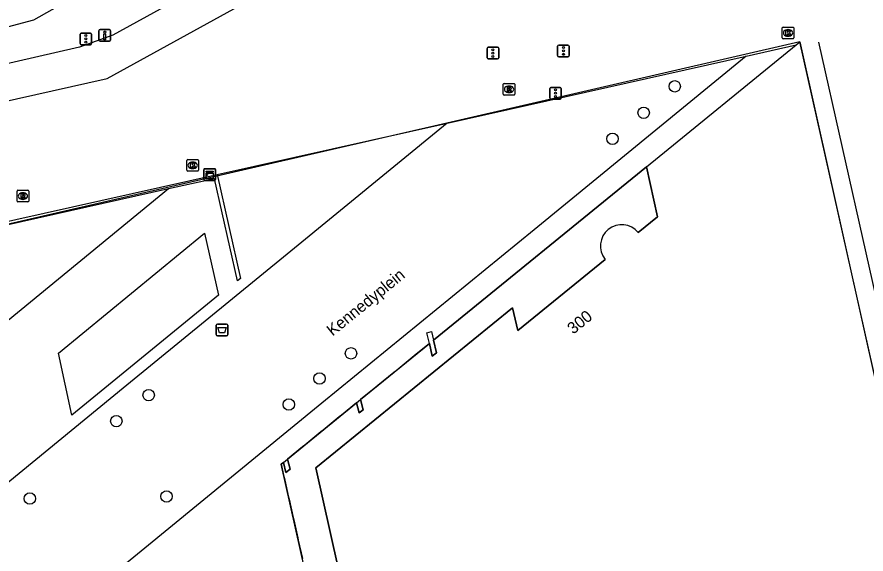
# Model space of a CAD drawing. Extents: x 160806 to 161707, y 383697 to 384148.
# Drawn here: x 161489.3 to 161561.9, y 383910.2 to 383956.1 of the extents above; entities that cross this region are included whole.
import ezdxf

# ---------------------------------------------------------------- set-up
doc = ezdxf.new("R2010")
doc.units = 0
for name, color, linetype in [('IMGEO_Afvalbak', 7, 'Continuous'), ('IMGEO_Boom', 7, 'Continuous'), ('IMGEO_Drukknoppaal', 7, 'Continuous'), ('IMGEO_Kast', 7, 'Continuous'), ('IMGEO_Kolk', 7, 'Continuous'), ('IMGEO_Lijnafwatering', 7, 'Continuous'), ('IMGEO_Muur', 7, 'Continuous'), ('IMGEO_Openbare_ruimte_label', 7, 'Continuous'), ('IMGEO_OVBaan_gesloten', 7, 'Continuous'), ('IMGEO_Pand', 7, 'Continuous'), ('IMGEO_Pand_nummerreeks', 7, 'Continuous'), ('IMGEO_Pand_overbouw', 7, 'Continuous'), ('IMGEO_Rijbaan_lokaal_gesloten', 7, 'Continuous'), ('IMGEO_Rioolput', 7, 'Continuous'), ('IMGEO_Verkeersregelinstallatiepaal', 7, 'Continuous'), ('IMGEO_Voetpad_open', 7, 'Continuous')]:
    doc.layers.add(name, color=color, linetype=linetype)

msp = doc.modelspace()

# ---------------------------------------------------------------- linework, layer by layer
at = {"layer": 'IMGEO_Afvalbak'}
for p, q in [((161506.372, 383928.933), (161506.372, 383929.733)), ((161506.372, 383929.733), (161506.372, 383928.933)), ((161506.472, 383929.833), (161507.262, 383929.833)), ((161507.262, 383929.833), (161506.472, 383929.833)), ((161507.362, 383929.733), (161507.362, 383928.933)), ((161507.362, 383928.933), (161507.362, 383929.733)), ((161507.262, 383928.833), (161506.472, 383928.833)), ((161506.472, 383928.833), (161507.262, 383928.833))]:
    msp.add_line(p, q, dxfattribs=at)
msp.add_lwpolyline([(161506.515, 383929.547), (161507.219, 383929.547), (161507.07, 383929.077), (161506.664, 383929.077), (161506.515, 383929.547)], dxfattribs=at)
for centre, start, end in [((161506.472, 383929.733), 90, 180), ((161506.472, 383929.733), 90, 180), ((161507.262, 383929.733), 0, 90), ((161507.262, 383929.733), 360, 90), ((161506.472, 383928.933), 180, 270), ((161506.472, 383928.933), 180, 270), ((161507.262, 383928.933), 270, 0), ((161507.262, 383928.933), 270, 0)]:
    msp.add_arc(centre, 0.1, start, end, dxfattribs=at)
at = {"layer": 'IMGEO_Boom'}
for centre in [(161545.585, 383950.166), (161542.926, 383947.907), (161540.266, 383945.685), (161517.898, 383927.324), (161515.202, 383925.175), (161500.593, 383923.754), (161512.579, 383922.952), (161497.824, 383921.531), (161490.429, 383914.901), (161502.123, 383915.083)]:
    msp.add_circle(centre, 0.489, dxfattribs=at)
at = {"layer": 'IMGEO_Drukknoppaal'}
for p, q in [((161496.34, 383954.127), (161496.34, 383954.927)), ((161496.34, 383954.927), (161496.34, 383954.127)), ((161496.44, 383955.027), (161497.23, 383955.027)), ((161497.23, 383955.027), (161496.44, 383955.027)), ((161497.33, 383954.927), (161497.33, 383954.127)), ((161497.33, 383954.127), (161497.33, 383954.927)), ((161497.23, 383954.027), (161496.44, 383954.027)), ((161496.44, 383954.027), (161497.23, 383954.027))]:
    msp.add_line(p, q, dxfattribs=at)
msp.add_lwpolyline([(161496.91, 383954.652), (161496.91, 383954.152), (161496.76, 383954.152), (161496.76, 383954.652), (161496.91, 383954.652)], dxfattribs=at)
msp.add_circle((161496.835, 383954.817), 0.085, dxfattribs=at)
for centre, start, end in [((161496.44, 383954.927), 90, 180), ((161496.44, 383954.927), 90, 180), ((161497.23, 383954.927), 0, 90), ((161497.23, 383954.927), 360, 90), ((161496.44, 383954.127), 180, 270), ((161496.44, 383954.127), 180, 270), ((161497.23, 383954.127), 270, 0), ((161497.23, 383954.127), 270, 0)]:
    msp.add_arc(centre, 0.1, start, end, dxfattribs=at)
at = {"layer": 'IMGEO_Kast'}
for p, q in [((161505.305, 383942.198), (161505.305, 383943.039)), ((161505.305, 383943.039), (161505.305, 383942.198)), ((161505.38, 383943.123), (161506.221, 383943.123)), ((161506.221, 383943.123), (161505.38, 383943.123)), ((161506.305, 383943.048), (161506.305, 383942.207)), ((161506.305, 383942.207), (161506.305, 383943.048)), ((161506.23, 383942.123), (161505.389, 383942.123)), ((161505.389, 383942.123), (161506.23, 383942.123))]:
    msp.add_line(p, q, dxfattribs=at)
for points in [[(161505.5, 383942.913), (161506.1, 383942.913), (161506.1, 383942.828), (161505.5, 383942.828), (161505.5, 383942.913)], [(161505.5, 383942.738), (161506.1, 383942.738), (161506.1, 383942.249), (161505.5, 383942.249), (161505.5, 383942.738)]]:
    msp.add_lwpolyline(points, dxfattribs=at)
msp.add_circle((161505.584, 383942.587), 0.0377, dxfattribs=at)
for centre, start, end in [((161505.383, 383943.045), 92.4484, 184.28452), ((161505.383, 383943.045), 92.4484, 184.28452), ((161506.227, 383943.045), 2.4484, 94.28452), ((161506.227, 383943.045), 2.4484, 94.28452), ((161505.383, 383942.201), 182.4484, 274.28452), ((161505.383, 383942.201), 182.4484, 274.28452), ((161506.227, 383942.201), 272.4484, 4.28452), ((161506.227, 383942.201), 272.4484, 4.28452)]:
    msp.add_arc(centre, 0.0779, start, end, dxfattribs=at)
at = {"layer": 'IMGEO_Kolk'}
for p, q in [((161554.774, 383954.312), (161554.774, 383955.164)), ((161554.849, 383955.238), (161555.701, 383955.238)), ((161555.262, 383955.018), (161555.287, 383955.018)), ((161555.775, 383955.164), (161555.775, 383954.312)), ((161555.701, 383954.238), (161554.849, 383954.238)), ((161555.285, 383954.458), (161555.26, 383954.458)), ((161503.856, 383942.985), (161503.856, 383943.837)), ((161503.931, 383943.911), (161504.783, 383943.911)), ((161504.344, 383943.691), (161504.369, 383943.691)), ((161504.857, 383943.837), (161504.857, 383942.985)), ((161504.783, 383942.911), (161503.931, 383942.911)), ((161504.367, 383943.131), (161504.342, 383943.131))]:
    msp.add_line(p, q, dxfattribs=at)
for points in [[(161554.774, 383954.312), (161554.774, 383955.164)], [(161554.849, 383955.238), (161555.701, 383955.238)], [(161555.095, 383954.938), (161555.218, 383954.938), (161555.218, 383954.787), (161555.348, 383954.938), (161555.512, 383954.938), (161555.366, 383954.787), (161555.519, 383954.538), (161555.367, 383954.538), (161555.282, 383954.702), (161555.218, 383954.635), (161555.218, 383954.538), (161555.095, 383954.538), (161555.095, 383954.938)], [(161555.775, 383955.164), (161555.775, 383954.312)], [(161555.701, 383954.238), (161554.849, 383954.238)], [(161503.856, 383942.985), (161503.856, 383943.837)], [(161503.931, 383943.911), (161504.783, 383943.911)], [(161504.177, 383943.611), (161504.3, 383943.611), (161504.3, 383943.46), (161504.43, 383943.611), (161504.594, 383943.611), (161504.448, 383943.46), (161504.601, 383943.211), (161504.449, 383943.211), (161504.364, 383943.375), (161504.3, 383943.308), (161504.3, 383943.211), (161504.177, 383943.211), (161504.177, 383943.611)], [(161504.857, 383943.837), (161504.857, 383942.985)], [(161504.783, 383942.911), (161503.931, 383942.911)]]:
    msp.add_lwpolyline(points, dxfattribs=at)
for centre, start, end in [((161554.851, 383955.162), 91.55205, 178.44795), ((161554.851, 383955.162), 91.55205, 178.44795), ((161555.699, 383955.162), 1.55205, 88.44795), ((161555.699, 383955.162), 1.55205, 88.44795), ((161554.851, 383954.314), 181.55205, 268.44795), ((161554.851, 383954.314), 181.55205, 268.44795), ((161555.699, 383954.314), 271.55205, 358.44795), ((161555.699, 383954.314), 271.55205, 358.44795), ((161503.933, 383943.835), 91.55205, 178.44795), ((161503.933, 383943.835), 91.55205, 178.44795), ((161504.781, 383943.835), 1.55205, 88.44795), ((161504.781, 383943.835), 1.55205, 88.44795), ((161503.933, 383942.987), 181.55205, 268.44795), ((161503.933, 383942.987), 181.55205, 268.44795), ((161504.781, 383942.987), 271.55205, 358.44795), ((161504.781, 383942.987), 271.55205, 358.44795)]:
    msp.add_arc(centre, 0.0765, start, end, dxfattribs=at)
for centre, major_axis, ratio, start_param, end_param in [((161555.261, 383954.738), (-0.387, 0.002), 0.722429, 4.712389, 7.853982), ((161555.286, 383954.738), (-0.39, 0.002), 0.717154, 1.570796, 4.712389), ((161504.343, 383943.411), (-0.387, 0.002), 0.722429, 4.712389, 7.853982), ((161504.368, 383943.411), (-0.39, 0.002), 0.717154, 1.570796, 4.712389)]:
    msp.add_ellipse(centre, major_axis=major_axis, ratio=ratio, start_param=start_param, end_param=end_param, dxfattribs=at)
at = {"layer": 'IMGEO_Lijnafwatering'}
for points in [[(161557.895, 383953.938), (161561.936, 383935.924)], [(161551.704, 383952.753), (161533.558, 383937.906)], [(161526.128, 383947.032), (161512.429, 383935.821)], [(161502.28, 383941.387), (161486.939, 383928.817)], [(161533.558, 383937.906), (161515.412, 383923.059)], [(161512.429, 383935.821), (161498.731, 383924.609)], [(161561.936, 383935.924), (161565.976, 383917.91)], [(161498.731, 383924.609), (161485.032, 383913.398)], [(161515.412, 383923.059), (161497.266, 383908.212)]]:
    msp.add_lwpolyline(points, dxfattribs=at)
at = {"layer": 'IMGEO_Muur'}
for points in [[(161454.756, 383931.084), (161506.454, 383942.63)], [(161506.454, 383942.63), (161508.439, 383933.738), (161508.183, 383933.535), (161506.222, 383942.268), (161502.28, 383941.387), (161484.102, 383937.319), (161484.378, 383936.019), (161477.167, 383934.318), (161476.856, 383935.709), (161454.819, 383930.799)]]:
    msp.add_lwpolyline(points, dxfattribs=at)
at = {"layer": 'IMGEO_OVBaan_gesloten'}
msp.add_lwpolyline([(161480.443, 383953.13), (161490.782, 383955.856), (161498.607, 383960.307), (161519.443, 383971.749)], dxfattribs=at)
at = {"layer": 'IMGEO_Pand'}
for points in [[(161543.162, 383943.281), (161555.972, 383953.708)], [(161555.972, 383953.708), (161556.299, 383953.974), (161562.871, 383924.395), (161563.33, 383924.497), (161577.028, 383863.632), (161576.544, 383863.524)], [(161543.162, 383943.281), (161544.114, 383939.013), (161542.463, 383937.675)], [(161539.638, 383935.367), (161532.156, 383929.275), (161531.72, 383931.221), (161514.903, 383917.532), (161521.152, 383889.432), (161518.425, 383888.826)], [(161524.603, 383928.164), (161524.393, 383929.092), (161524.791, 383929.187), (161524.957, 383928.451)], [(161524.603, 383928.164), (161524.849, 383927.077), (161525.203, 383927.357), (161524.957, 383928.451)], [(161518.377, 383923.091), (161518.722, 383923.384)], [(161518.377, 383923.091), (161518.585, 383922.232), (161518.924, 383922.501), (161518.722, 383923.384)], [(161512.128, 383917.99), (161512.48, 383918.284)], [(161512.128, 383917.99), (161512.33, 383917.119), (161512.682, 383917.413), (161512.48, 383918.284)]]:
    msp.add_lwpolyline(points, dxfattribs=at)
msp.add_arc((161541.06, 383936.509), 1.824, 39.719, 218.77804, dxfattribs=at)
at = {"layer": 'IMGEO_Pand_overbouw'}
msp.add_lwpolyline([(161576.544, 383863.524), (161556.299, 383953.974), (161403.923, 383918.874), (161417.58, 383859.039), (161456.542, 383836.683)], close=True, dxfattribs=at)
for points in [[(161542.463, 383937.675), (161544.114, 383939.013), (161543.162, 383943.281), (161524.957, 383928.451), (161525.203, 383927.357), (161524.849, 383927.077), (161524.603, 383928.164), (161523.307, 383927.113), (161523.125, 383926.96), (161521.751, 383925.839), (161521.569, 383925.688), (161520.187, 383924.579), (161520.009, 383924.429), (161518.722, 383923.384), (161518.924, 383922.501), (161518.585, 383922.232), (161518.377, 383923.091), (161517.073, 383922.029), (161516.886, 383921.882), (161515.513, 383920.754), (161515.329, 383920.601), (161513.944, 383919.481), (161513.761, 383919.329), (161512.48, 383918.284), (161512.682, 383917.413), (161512.33, 383917.119), (161512.128, 383917.99)], [(161521.152, 383889.432), (161514.903, 383917.532), (161531.72, 383931.221), (161532.156, 383929.275), (161539.638, 383935.367)], [(161512.128, 383917.99), (161511.932, 383917.834), (161512.164, 383916.794), (161512.207, 383916.608), (161512.559, 383915.03), (161512.602, 383914.843), (161512.953, 383913.273), (161512.995, 383913.087), (161513.344, 383911.529), (161513.386, 383911.342), (161513.739, 383909.761)]]:
    msp.add_lwpolyline(points, dxfattribs=at)
msp.add_arc((161541.06, 383936.509), 1.824, 39.719, 218.77804, dxfattribs=at)
at = {"layer": 'IMGEO_Rijbaan_lokaal_gesloten'}
for points in [[(161515.493, 383964.453), (161497.52, 383954.56), (161494.69, 383953.527), (161485.579, 383951.426)], [(161486.216, 383948.419), (161497.049, 383950.841), (161515.872, 383961.211)], [(161506.454, 383942.63), (161526.128, 383947.032), (161551.704, 383952.753), (161555.972, 383953.708)]]:
    msp.add_lwpolyline(points, dxfattribs=at)
at = {"layer": 'IMGEO_Rioolput'}
for p, q in [((161530.915, 383949.49), (161530.915, 383950.342)), ((161530.99, 383950.416), (161531.842, 383950.416)), ((161531.403, 383950.196), (161531.428, 383950.196)), ((161531.916, 383950.342), (161531.916, 383949.49)), ((161531.842, 383949.416), (161530.99, 383949.416)), ((161531.426, 383949.636), (161531.401, 383949.636)), ((161489.335, 383940.355), (161489.335, 383941.207)), ((161489.41, 383941.281), (161490.262, 383941.281)), ((161489.823, 383941.061), (161489.848, 383941.061)), ((161490.336, 383941.207), (161490.336, 383940.355)), ((161489.846, 383940.501), (161489.821, 383940.501)), ((161490.262, 383940.281), (161489.41, 383940.281))]:
    msp.add_line(p, q, dxfattribs=at)
for points in [[(161530.915, 383949.49), (161530.915, 383950.342)], [(161530.99, 383950.416), (161531.842, 383950.416)], [(161531.504, 383950.114), (161531.252, 383950.116), (161531.252, 383949.716)], [(161531.252, 383949.716), (161531.376, 383949.716), (161531.376, 383949.878), (161531.387, 383949.878)], [(161531.43, 383950.035), (161531.376, 383950.035), (161531.376, 383949.954)], [(161531.376, 383949.954), (161531.428, 383949.954)], [(161531.434, 383949.849), (161531.505, 383949.716), (161531.645, 383949.716), (161531.58, 383949.842)], [(161531.916, 383950.342), (161531.916, 383949.49)], [(161531.842, 383949.416), (161530.99, 383949.416)], [(161489.335, 383940.355), (161489.335, 383941.207)], [(161489.41, 383941.281), (161490.262, 383941.281)], [(161490.336, 383941.207), (161490.336, 383940.355)], [(161489.924, 383940.979), (161489.672, 383940.981), (161489.672, 383940.581)], [(161489.672, 383940.581), (161489.796, 383940.581), (161489.796, 383940.743), (161489.807, 383940.743)], [(161489.85, 383940.9), (161489.796, 383940.9), (161489.796, 383940.819)], [(161489.796, 383940.819), (161489.848, 383940.819)], [(161489.854, 383940.714), (161489.925, 383940.581), (161490.065, 383940.581), (161490, 383940.707)], [(161490.262, 383940.281), (161489.41, 383940.281)]]:
    msp.add_lwpolyline(points, dxfattribs=at)
for centre, radius, start, end in [((161530.992, 383950.34), 0.0765, 91.55205, 178.44795), ((161530.992, 383950.34), 0.0765, 91.55205, 178.44795), ((161531.386, 383949.825), 0.0533, 26.02933, 88.69889), ((161531.412, 383950.143), 0.19, 274.7715, 282.96867), ((161531.436, 383949.939), 0.0964, 77.00612, 93.18647), ((161531.45, 383949.996), 0.0378, 276.66336, 79.67722), ((161531.503, 383950.004), 0.109, 350.36119, 89.41601), ((161531.501, 383950.004), 0.112, 277.58423, 350.98172), ((161531.485, 383949.789), 0.108, 29.51342, 73.79051), ((161531.84, 383950.34), 0.0765, 1.55205, 88.44795), ((161531.84, 383950.34), 0.0765, 1.55205, 88.44795), ((161530.992, 383949.492), 0.0765, 181.55205, 268.44795), ((161530.992, 383949.492), 0.0765, 181.55205, 268.44795), ((161531.84, 383949.492), 0.0765, 271.55205, 358.44795), ((161531.84, 383949.492), 0.0765, 271.55205, 358.44795), ((161489.412, 383941.205), 0.0765, 91.55205, 178.44795), ((161489.412, 383941.205), 0.0765, 91.55205, 178.44795), ((161490.26, 383941.205), 0.0765, 1.55205, 88.44795), ((161490.26, 383941.205), 0.0765, 1.55205, 88.44795), ((161489.412, 383940.357), 0.0765, 181.55205, 268.44795), ((161489.412, 383940.357), 0.0765, 181.55205, 268.44795), ((161489.806, 383940.69), 0.0533, 26.02933, 88.69889), ((161489.832, 383941.008), 0.19, 274.7715, 282.96867), ((161489.856, 383940.804), 0.0964, 77.00612, 93.18647), ((161489.87, 383940.861), 0.0378, 276.66336, 79.67722), ((161489.923, 383940.869), 0.109, 350.36119, 89.41601), ((161489.921, 383940.869), 0.112, 277.58423, 350.98172), ((161489.905, 383940.654), 0.108, 29.51342, 73.79051), ((161490.26, 383940.357), 0.0765, 271.55205, 358.44795), ((161490.26, 383940.357), 0.0765, 271.55205, 358.44795)]:
    msp.add_arc(centre, radius, start, end, dxfattribs=at)
for centre, major_axis, ratio, start_param, end_param in [((161531.402, 383949.916), (-0.387, 0.002), 0.722429, 4.712389, 7.853982), ((161531.427, 383949.916), (-0.39, 0.002), 0.717154, 1.570796, 4.712389), ((161489.822, 383940.781), (-0.387, 0.002), 0.722429, 4.712389, 7.853982), ((161489.847, 383940.781), (-0.39, 0.002), 0.717154, 1.570796, 4.712389)]:
    msp.add_ellipse(centre, major_axis=major_axis, ratio=ratio, start_param=start_param, end_param=end_param, dxfattribs=at)
at = {"layer": 'IMGEO_Verkeersregelinstallatiepaal'}
for p, q in [((161494.725, 383953.83), (161494.725, 383954.63)), ((161494.725, 383954.63), (161494.725, 383953.83)), ((161494.825, 383954.73), (161495.615, 383954.73)), ((161495.615, 383954.73), (161494.825, 383954.73)), ((161495.715, 383954.63), (161495.715, 383953.83)), ((161495.715, 383953.83), (161495.715, 383954.63)), ((161495.615, 383953.73), (161494.825, 383953.73)), ((161494.825, 383953.73), (161495.615, 383953.73)), ((161529.542, 383952.612), (161529.542, 383953.412)), ((161529.542, 383953.412), (161529.542, 383952.612)), ((161529.642, 383953.512), (161530.432, 383953.512)), ((161530.432, 383953.512), (161529.642, 383953.512)), ((161530.532, 383953.412), (161530.532, 383952.612)), ((161530.532, 383952.612), (161530.532, 383953.412)), ((161535.566, 383952.797), (161535.566, 383953.597)), ((161535.566, 383953.597), (161535.566, 383952.797)), ((161535.666, 383953.697), (161536.456, 383953.697)), ((161536.456, 383953.697), (161535.666, 383953.697)), ((161536.556, 383953.597), (161536.556, 383952.797)), ((161536.556, 383952.797), (161536.556, 383953.597)), ((161536.456, 383952.697), (161535.666, 383952.697)), ((161535.666, 383952.697), (161536.456, 383952.697)), ((161530.432, 383952.512), (161529.642, 383952.512)), ((161529.642, 383952.512), (161530.432, 383952.512)), ((161534.891, 383949.181), (161534.891, 383949.981)), ((161534.891, 383949.981), (161534.891, 383949.181)), ((161534.991, 383950.081), (161535.781, 383950.081)), ((161535.781, 383950.081), (161534.991, 383950.081)), ((161535.881, 383949.981), (161535.881, 383949.181)), ((161535.881, 383949.181), (161535.881, 383949.981)), ((161535.781, 383949.081), (161534.991, 383949.081)), ((161534.991, 383949.081), (161535.781, 383949.081))]:
    msp.add_line(p, q, dxfattribs=at)
for centre in [(161495.22, 383954.52), (161495.22, 383954.23), (161495.22, 383953.94), (161530.037, 383953.302), (161536.061, 383953.487), (161530.037, 383953.012), (161530.037, 383952.722), (161536.061, 383953.197), (161536.061, 383952.907), (161535.386, 383949.871), (161535.386, 383949.581), (161535.386, 383949.291)]:
    msp.add_circle(centre, 0.085, dxfattribs=at)
for centre, start, end in [((161494.825, 383954.63), 90, 180), ((161494.825, 383954.63), 90, 180), ((161495.615, 383954.63), 0, 90), ((161495.615, 383954.63), 360, 90), ((161494.825, 383953.83), 180, 270), ((161494.825, 383953.83), 180, 270), ((161495.615, 383953.83), 270, 0), ((161495.615, 383953.83), 270, 0), ((161529.642, 383953.412), 90, 180), ((161529.642, 383953.412), 90, 180), ((161530.432, 383953.412), 0, 90), ((161530.432, 383953.412), 360, 90), ((161535.666, 383953.597), 90, 180), ((161535.666, 383953.597), 90, 180), ((161536.456, 383953.597), 0, 90), ((161536.456, 383953.597), 360, 90), ((161535.666, 383952.797), 180, 270), ((161535.666, 383952.797), 180, 270), ((161536.456, 383952.797), 270, 0), ((161536.456, 383952.797), 270, 0), ((161529.642, 383952.612), 180, 270), ((161529.642, 383952.612), 180, 270), ((161530.432, 383952.612), 270, 0), ((161530.432, 383952.612), 270, 0), ((161534.991, 383949.981), 90, 180), ((161534.991, 383949.981), 90, 180), ((161535.781, 383949.981), 0, 90), ((161535.781, 383949.981), 360, 90), ((161534.991, 383949.181), 180, 270), ((161534.991, 383949.181), 180, 270), ((161535.781, 383949.181), 270, 0), ((161535.781, 383949.181), 270, 0)]:
    msp.add_arc(centre, 0.1, start, end, dxfattribs=at)
at = {"layer": 'IMGEO_Voetpad_open'}
for points in [[(161524.957, 383928.451), (161543.162, 383943.281)], [(161494.03, 383922.036), (161492.872, 383927.352), (161505.371, 383937.593), (161506.572, 383932.289), (161494.03, 383922.036)], [(161518.722, 383923.384), (161524.603, 383928.164)], [(161512.48, 383918.284), (161518.377, 383923.091)], [(161518.425, 383888.826), (161511.932, 383917.834), (161512.128, 383917.99)]]:
    msp.add_lwpolyline(points, dxfattribs=at)

# ---------------------------------------------------------------- texts
at = {"layer": 'IMGEO_Openbare_ruimte_label'}
msp.add_text('Kennedyplein', height=1, rotation=39.19669, dxfattribs=at).set_placement((161516.324, 383928.749))
at = {"layer": 'IMGEO_Pand_nummerreeks'}
msp.add_text('300', height=1, rotation=39.1532, dxfattribs=at).set_placement((161536.904, 383928.911))

doc.saveas('drawing.dxf')
